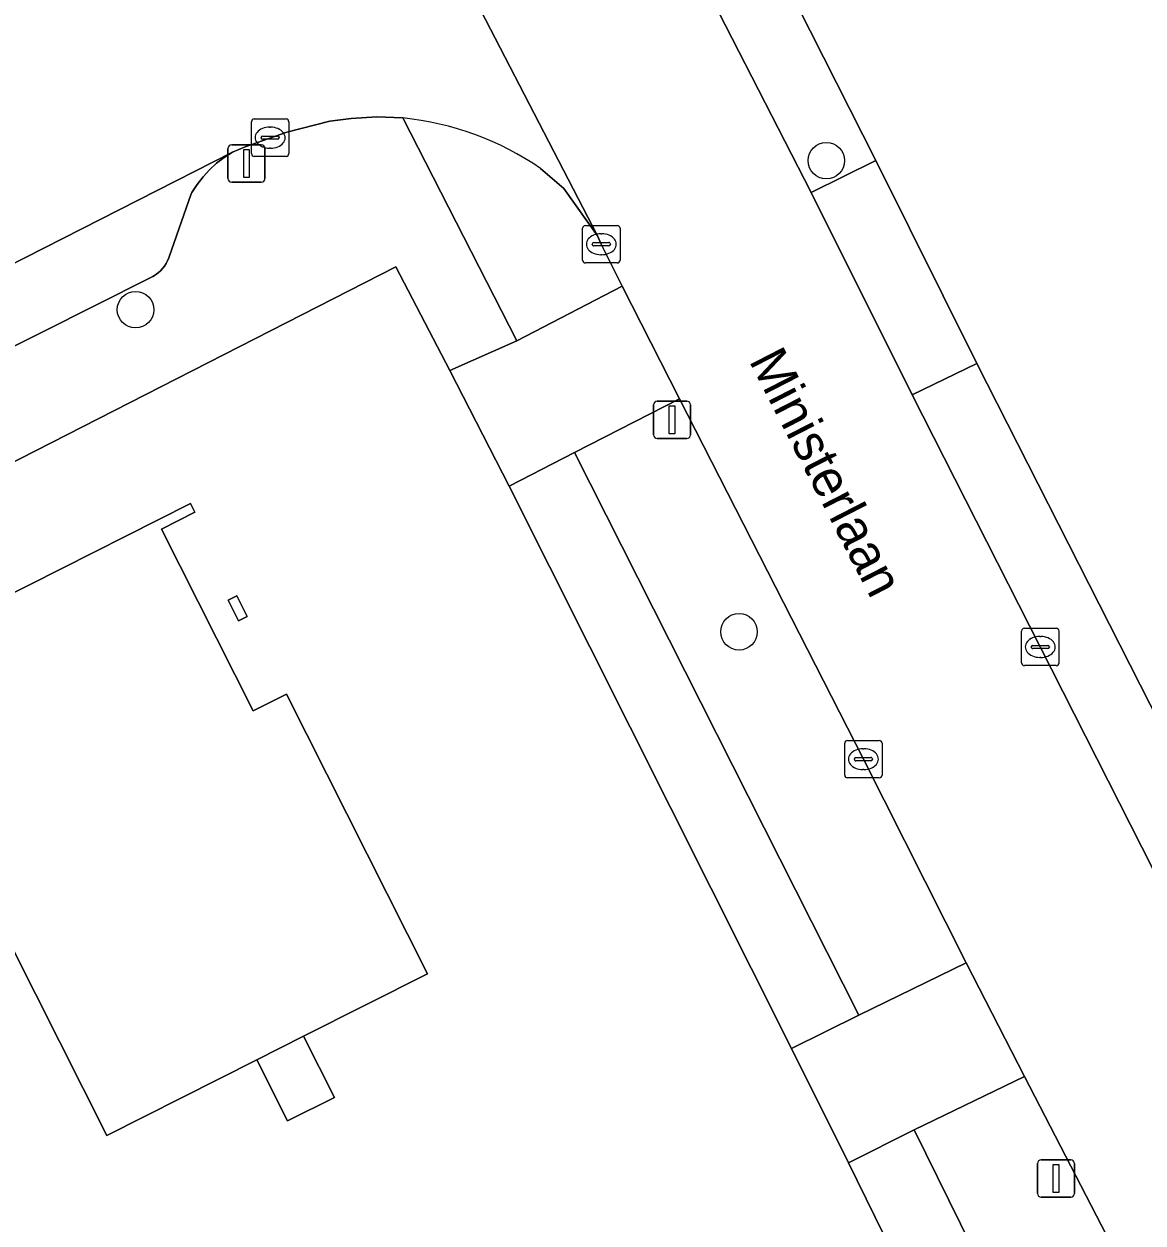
# Model space of a CAD drawing. Extents: x 162722 to 165104, y 384719 to 386284.
# Drawn here: x 163672.34 to 163702.28, y 384951.29 to 384983.38 of the extents above; entities that cross this region are included whole.
import ezdxf

# ---------------------------------------------------------------- set-up
doc = ezdxf.new("R2010")
doc.units = 0
for name, color, linetype in [('IMGEO_Boom', 7, 'Continuous'), ('IMGEO_Erf', 7, 'Continuous'), ('IMGEO_Groenvoorziening', 7, 'Continuous'), ('IMGEO_Kolk', 7, 'Continuous'), ('IMGEO_Lichtmast', 7, 'Continuous'), ('IMGEO_Openbare_ruimte_label', 7, 'Continuous'), ('IMGEO_Pand', 7, 'Continuous'), ('IMGEO_Parkeervlak_open', 7, 'Continuous'), ('IMGEO_Rijbaan_lokaal_open', 7, 'Continuous'), ('IMGEO_Verkeerseiland_groen', 7, 'Continuous'), ('IMGEO_Voetpad_open', 7, 'Continuous')]:
    doc.layers.add(name, color=color, linetype=linetype)

msp = doc.modelspace()

# ---------------------------------------------------------------- linework, layer by layer
at = {"layer": 'IMGEO_Boom'}
for centre in [(163693.809, 384979.719), (163675.327, 384975.73), (163691.473, 384967.11)]:
    msp.add_circle(centre, 0.489, dxfattribs=at)
at = {"layer": 'IMGEO_Erf'}
for points in [[(163757.669, 384995.182), (163755.228, 385000), (163754.144, 385002.139), (163753.91, 385002.58), (163753.157, 385003.995), (163752.338, 385003.569), (163740.176, 385027.426), (163738.567, 385026.557), (163738.822, 385026.058), (163738.155, 385025.71), (163714.087, 385013.147), (163707.49, 385026.219), (163704.586, 385031.975), (163675.935, 385017.371), (163676.458, 385016.283), (163679.164, 385010.981), (163682.06, 385005.355), (163684.816, 385000), (163686.673, 384996.393), (163688.473, 384992.888), (163695.133, 384979.723), (163697.839, 384974.289), (163705.48, 384959.251), (163707.512, 384955.385)], [(163689.085, 384888.134), (163687.084, 384890.632), (163676.468, 384903.753), (163673.969, 384906.848), (163673.753, 384907.134), (163665.55, 384917.268), (163665.421, 384917.261), (163660.75, 384923.114), (163663.751, 384924.681), (163669.399, 384920.052), (163676.37, 384925.254), (163699.363, 384942.796), (163694.404, 384952.9), (163692.876, 384955.959), (163685.319, 384971.004), (163683.732, 384974.099), (163682.29, 384976.876), (163639.563, 384955.061), (163635.539, 384952.364), (163633.451, 384950.624), (163627.464, 384944.399)]]:
    msp.add_lwpolyline(points, dxfattribs=at)
for points in [[(163679.396, 384954.019), (163678.57, 384955.657), (163674.556, 384953.632), (163671.374, 384959.94), (163662.971, 384955.701), (163662.466, 384956.703), (163660.215, 384961.167), (163666.964, 384964.571), (163667.958, 384962.602), (163669.574, 384963.417), (163668.587, 384965.373), (163668.173, 384966.193), (163676.793, 384970.541), (163676.91, 384970.309), (163676.019, 384969.859), (163678.473, 384964.994), (163679.364, 384965.444), (163683.138, 384957.961), (163679.824, 384956.289), (163680.65, 384954.651)], [(163677.805, 384967.96), (163678.036, 384968.077), (163678.315, 384967.523), (163678.084, 384967.407)]]:
    msp.add_lwpolyline(points, close=True, dxfattribs=at)
at = {"layer": 'IMGEO_Groenvoorziening'}
msp.add_lwpolyline([(163697.55, 384958.253), (163694.801, 384963.702), (163689.884, 384973.343), (163687.069, 384971.907), (163694.677, 384956.848)], close=True, dxfattribs=at)
msp.add_lwpolyline([(163703.08, 384947.428), (163701.856, 384949.895), (163699.111, 384955.206), (163696.161, 384953.784), (163702.06, 384941.801)], dxfattribs=at)
at = {"layer": 'IMGEO_Kolk'}
for p, q in [((163678.427, 384979.908), (163678.427, 384980.76)), ((163678.502, 384980.834), (163679.354, 384980.834)), ((163679.428, 384980.76), (163679.428, 384979.908)), ((163678.686, 384980.328), (163678.686, 384980.34)), ((163678.729, 384980.377), (163679.127, 384980.377)), ((163678.915, 384980.614), (163678.94, 384980.614)), ((163679.17, 384980.34), (163679.17, 384980.328)), ((163679.124, 384980.291), (163678.726, 384980.291)), ((163678.938, 384980.054), (163678.913, 384980.054)), ((163679.354, 384979.834), (163678.502, 384979.834)), ((163687.288, 384977.056), (163687.288, 384977.908)), ((163687.363, 384977.982), (163688.215, 384977.982)), ((163687.776, 384977.762), (163687.801, 384977.762)), ((163688.289, 384977.908), (163688.289, 384977.056)), ((163687.547, 384977.476), (163687.547, 384977.488)), ((163687.985, 384977.439), (163687.587, 384977.439)), ((163687.59, 384977.525), (163687.988, 384977.525)), ((163688.031, 384977.488), (163688.031, 384977.476)), ((163687.799, 384977.202), (163687.774, 384977.202)), ((163688.215, 384976.982), (163687.363, 384976.982)), ((163699.108, 384967.204), (163699.96, 384967.204)), ((163699.033, 384966.278), (163699.033, 384967.13)), ((163699.521, 384966.984), (163699.546, 384966.984)), ((163700.034, 384967.13), (163700.034, 384966.278)), ((163699.292, 384966.698), (163699.292, 384966.71)), ((163699.73, 384966.661), (163699.332, 384966.661)), ((163699.335, 384966.747), (163699.733, 384966.747)), ((163699.776, 384966.71), (163699.776, 384966.698)), ((163699.96, 384966.204), (163699.108, 384966.204)), ((163699.544, 384966.424), (163699.519, 384966.424)), ((163694.3, 384963.276), (163694.3, 384964.128)), ((163694.375, 384964.202), (163695.227, 384964.202)), ((163694.788, 384963.982), (163694.813, 384963.982)), ((163695.301, 384964.128), (163695.301, 384963.276)), ((163694.559, 384963.696), (163694.559, 384963.708)), ((163694.997, 384963.659), (163694.599, 384963.659)), ((163694.602, 384963.745), (163695, 384963.745)), ((163695.043, 384963.708), (163695.043, 384963.696)), ((163694.811, 384963.422), (163694.786, 384963.422)), ((163695.227, 384963.202), (163694.375, 384963.202))]:
    msp.add_line(p, q, dxfattribs=at)
for points in [[(163678.427, 384979.908), (163678.427, 384980.76)], [(163678.502, 384980.834), (163679.354, 384980.834)], [(163679.428, 384980.76), (163679.428, 384979.908)], [(163679.354, 384979.834), (163678.502, 384979.834)], [(163687.288, 384977.056), (163687.288, 384977.908)], [(163687.363, 384977.982), (163688.215, 384977.982)], [(163688.289, 384977.908), (163688.289, 384977.056)], [(163688.215, 384976.982), (163687.363, 384976.982)], [(163699.108, 384967.204), (163699.96, 384967.204)], [(163699.033, 384966.278), (163699.033, 384967.13)], [(163700.034, 384967.13), (163700.034, 384966.278)], [(163699.96, 384966.204), (163699.108, 384966.204)], [(163694.3, 384963.276), (163694.3, 384964.128)], [(163694.375, 384964.202), (163695.227, 384964.202)], [(163695.301, 384964.128), (163695.301, 384963.276)], [(163695.227, 384963.202), (163694.375, 384963.202)]]:
    msp.add_lwpolyline(points, dxfattribs=at)
for centre, radius, start, end in [((163678.504, 384980.758), 0.0765, 91.552, 178.448), ((163678.504, 384980.758), 0.0765, 91.552, 178.448), ((163679.352, 384980.758), 0.0765, 1.552, 88.448), ((163679.352, 384980.758), 0.0765, 1.552, 88.448), ((163678.726, 384980.337), 0.0403, 85.8775, 175.7526), ((163678.723, 384980.327), 0.0366, 178.938, 274.7102), ((163679.127, 384980.334), 0.043, 264.8664, 352.4533), ((163679.131, 384980.339), 0.0386, 1.7309, 96.639), ((163678.504, 384979.91), 0.0765, 181.552, 268.448), ((163678.504, 384979.91), 0.0765, 181.552, 268.448), ((163679.352, 384979.91), 0.0765, 271.552, 358.448), ((163679.352, 384979.91), 0.0765, 271.552, 358.448), ((163687.365, 384977.906), 0.0765, 91.552, 178.448), ((163687.365, 384977.906), 0.0765, 91.552, 178.448), ((163688.213, 384977.906), 0.0765, 1.552, 88.448), ((163688.213, 384977.906), 0.0765, 1.552, 88.448), ((163687.587, 384977.485), 0.0403, 85.8775, 175.7526), ((163687.584, 384977.475), 0.0366, 178.938, 274.7102), ((163687.988, 384977.482), 0.043, 264.8664, 352.4533), ((163687.992, 384977.487), 0.0386, 1.7309, 96.639), ((163687.365, 384977.058), 0.0765, 181.552, 268.448), ((163687.365, 384977.058), 0.0765, 181.552, 268.448), ((163688.213, 384977.058), 0.0765, 271.552, 358.448), ((163688.213, 384977.058), 0.0765, 271.552, 358.448), ((163699.11, 384967.128), 0.0765, 91.552, 178.448), ((163699.11, 384967.128), 0.0765, 91.552, 178.448), ((163699.958, 384967.128), 0.0765, 1.552, 88.448), ((163699.958, 384967.128), 0.0765, 1.552, 88.448), ((163699.332, 384966.707), 0.0403, 85.8775, 175.7526), ((163699.329, 384966.697), 0.0366, 178.938, 274.7102), ((163699.733, 384966.704), 0.043, 264.8664, 352.4533), ((163699.737, 384966.709), 0.0386, 1.7309, 96.639), ((163699.11, 384966.28), 0.0765, 181.552, 268.448), ((163699.11, 384966.28), 0.0765, 181.552, 268.448), ((163699.958, 384966.28), 0.0765, 271.552, 358.448), ((163699.958, 384966.28), 0.0765, 271.552, 358.448), ((163694.377, 384964.126), 0.0765, 91.552, 178.448), ((163694.377, 384964.126), 0.0765, 91.552, 178.448), ((163695.225, 384964.126), 0.0765, 1.552, 88.448), ((163695.225, 384964.126), 0.0765, 1.552, 88.448), ((163694.599, 384963.705), 0.0403, 85.8775, 175.7526), ((163694.596, 384963.695), 0.0366, 178.938, 274.7102), ((163695, 384963.702), 0.043, 264.8664, 352.4533), ((163695.004, 384963.707), 0.0386, 1.7309, 96.639), ((163694.377, 384963.278), 0.0765, 181.552, 268.448), ((163694.377, 384963.278), 0.0765, 181.552, 268.448), ((163695.225, 384963.278), 0.0765, 271.552, 358.448), ((163695.225, 384963.278), 0.0765, 271.552, 358.448)]:
    msp.add_arc(centre, radius, start, end, dxfattribs=at)
for centre, major_axis, ratio, start_param, end_param in [((163678.914, 384980.334), (-0.387, 0.002), 0.722429, 4.712389, 7.853982), ((163678.939, 384980.334), (-0.39, 0.002), 0.717154, 1.570796, 4.712389), ((163687.775, 384977.482), (-0.387, 0.002), 0.722429, 4.712389, 7.853982), ((163687.8, 384977.482), (-0.39, 0.002), 0.717154, 1.570796, 4.712389), ((163699.52, 384966.704), (-0.387, 0.002), 0.722429, 4.712389, 7.853982), ((163699.545, 384966.704), (-0.39, 0.002), 0.717154, 1.570796, 4.712389), ((163694.787, 384963.702), (-0.387, 0.002), 0.722429, 4.712389, 7.853982), ((163694.812, 384963.702), (-0.39, 0.002), 0.717154, 1.570796, 4.712389)]:
    msp.add_ellipse(centre, major_axis=major_axis, ratio=ratio, start_param=start_param, end_param=end_param, dxfattribs=at)
at = {"layer": 'IMGEO_Lichtmast'}
for p, q in [((163677.8, 384979.242), (163677.8, 384980.042)), ((163677.8, 384980.042), (163677.8, 384979.242)), ((163677.9, 384980.142), (163678.69, 384980.142)), ((163678.69, 384980.142), (163677.9, 384980.142)), ((163678.79, 384980.042), (163678.79, 384979.242)), ((163678.79, 384979.242), (163678.79, 384980.042)), ((163678.69, 384979.142), (163677.9, 384979.142)), ((163677.9, 384979.142), (163678.69, 384979.142)), ((163689.287, 384973.285), (163690.077, 384973.285)), ((163690.077, 384973.285), (163689.287, 384973.285)), ((163689.187, 384972.385), (163689.187, 384973.185)), ((163689.187, 384973.185), (163689.187, 384972.385)), ((163690.177, 384973.185), (163690.177, 384972.385)), ((163690.177, 384972.385), (163690.177, 384973.185)), ((163690.077, 384972.285), (163689.287, 384972.285)), ((163689.287, 384972.285), (163690.077, 384972.285)), ((163699.457, 384952.08), (163699.457, 384952.88)), ((163699.457, 384952.88), (163699.457, 384952.08)), ((163699.557, 384952.98), (163700.347, 384952.98)), ((163700.347, 384952.98), (163699.557, 384952.98)), ((163700.447, 384952.88), (163700.447, 384952.08)), ((163700.447, 384952.08), (163700.447, 384952.88)), ((163700.347, 384951.98), (163699.557, 384951.98)), ((163699.557, 384951.98), (163700.347, 384951.98))]:
    msp.add_line(p, q, dxfattribs=at)
for points in [[(163678.22, 384980.017), (163678.37, 384980.017), (163678.37, 384979.267), (163678.22, 384979.267), (163678.22, 384980.017)], [(163689.607, 384973.16), (163689.757, 384973.16), (163689.757, 384972.41), (163689.607, 384972.41), (163689.607, 384973.16)], [(163699.877, 384952.855), (163700.027, 384952.855), (163700.027, 384952.105), (163699.877, 384952.105), (163699.877, 384952.855)]]:
    msp.add_lwpolyline(points, dxfattribs=at)
for centre, start, end in [((163677.9, 384980.042), 90, 180), ((163677.9, 384980.042), 90, 180), ((163678.69, 384980.042), 0, 90), ((163678.69, 384980.042), 360, 90), ((163677.9, 384979.242), 180, 270), ((163677.9, 384979.242), 180, 270), ((163678.69, 384979.242), 270, 0), ((163678.69, 384979.242), 270, 0), ((163689.287, 384973.185), 90, 180), ((163689.287, 384973.185), 90, 180), ((163690.077, 384973.185), 0, 90), ((163690.077, 384973.185), 360, 90), ((163689.287, 384972.385), 180, 270), ((163689.287, 384972.385), 180, 270), ((163690.077, 384972.385), 270, 0), ((163690.077, 384972.385), 270, 0), ((163699.557, 384952.88), 90, 180), ((163699.557, 384952.88), 90, 180), ((163700.347, 384952.88), 0, 90), ((163700.347, 384952.88), 360, 90), ((163699.557, 384952.08), 180, 270), ((163699.557, 384952.08), 180, 270), ((163700.347, 384952.08), 270, 0), ((163700.347, 384952.08), 270, 0)]:
    msp.add_arc(centre, 0.1, start, end, dxfattribs=at)
at = {"layer": 'IMGEO_Pand'}
for points in [[(163679.364, 384965.444), (163678.473, 384964.994), (163676.019, 384969.859), (163676.91, 384970.309), (163676.793, 384970.541), (163668.173, 384966.193), (163668.587, 384965.373), (163669.574, 384963.417), (163667.958, 384962.602), (163666.964, 384964.571), (163660.215, 384961.167), (163662.466, 384956.703), (163662.971, 384955.701), (163671.374, 384959.94), (163674.556, 384953.632), (163678.57, 384955.657), (163679.824, 384956.289), (163683.138, 384957.961)], [(163678.036, 384968.077), (163677.805, 384967.96), (163678.084, 384967.407), (163678.315, 384967.523)], [(163679.824, 384956.289), (163678.57, 384955.657), (163679.396, 384954.019), (163680.65, 384954.651)]]:
    msp.add_lwpolyline(points, close=True, dxfattribs=at)
at = {"layer": 'IMGEO_Parkeervlak_open'}
for points in [[(163695.133, 384979.723), (163688.473, 384992.888), (163686.744, 384992.011), (163689.884, 384985.748), (163693.405, 384978.87)], [(163705.48, 384959.251), (163697.839, 384974.289), (163696.103, 384973.454), (163699.534, 384966.704), (163703.768, 384958.355)]]:
    msp.add_lwpolyline(points, close=True, dxfattribs=at)
msp.add_lwpolyline([(163652.428, 384964.866), (163675.718, 384976.583), (163675.792, 384976.621), (163675.863, 384976.665), (163675.93, 384976.715), (163675.991, 384976.771), (163676.048, 384976.832), (163676.099, 384976.898), (163676.144, 384976.968), (163676.182, 384977.042), (163676.214, 384977.119), (163676.223, 384977.147), (163676.819, 384978.83), (163676.837, 384978.862), (163676.975, 384979.08), (163677.132, 384979.285), (163677.306, 384979.475), (163677.497, 384979.649), (163677.702, 384979.805), (163677.921, 384979.942), (163666.306, 384974.039)], dxfattribs=at)
at = {"layer": 'IMGEO_Rijbaan_lokaal_open'}
for points in [[(163686.166, 384979.51), (163686.783, 384978.976), (163687.684, 384977.706), (163679.873, 384992.805), (163679.812, 384992.892)], [(163679.873, 384992.805), (163687.684, 384977.706), (163687.789, 384977.482), (163688.346, 384976.358), (163689.884, 384973.343), (163694.801, 384963.702), (163697.55, 384958.253), (163699.111, 384955.206), (163701.856, 384949.895), (163703.08, 384947.428), (163709.401, 384938.391), (163712.452, 384935.454), (163725.854, 384922.399)], [(163707.281, 384951.821), (163705.797, 384954.524), (163703.768, 384958.355), (163699.534, 384966.704), (163696.103, 384973.454), (163693.405, 384978.87), (163689.884, 384985.748)], [(163666.306, 384974.039), (163677.921, 384979.942), (163678.259, 384980.084), (163679.377, 384980.48), (163680.527, 384980.775), (163681.095, 384980.851), (163681.787, 384980.887), (163682.479, 384980.861)]]:
    msp.add_lwpolyline(points, dxfattribs=at)
msp.add_arc((163681.688, 384972.996), 7.904, 55.4937, 84.2583, dxfattribs=at)
at = {"layer": 'IMGEO_Verkeerseiland_groen'}
for points in [[(163682.479, 384980.861), (163685.526, 384974.9), (163688.346, 384976.358), (163687.789, 384977.482), (163687.684, 384977.706), (163686.783, 384978.976)], [(163686.783, 384978.976), (163686.166, 384979.51)]]:
    msp.add_lwpolyline(points, dxfattribs=at)
msp.add_arc((163681.688, 384972.996), 7.904, 55.4937, 84.2583, dxfattribs=at)
at = {"layer": 'IMGEO_Voetpad_open'}
msp.add_lwpolyline([(163639.563, 384955.061), (163682.29, 384976.876), (163683.732, 384974.099), (163685.526, 384974.9), (163682.479, 384980.861), (163681.787, 384980.887), (163681.095, 384980.851), (163680.527, 384980.775), (163679.377, 384980.48), (163678.259, 384980.084), (163677.921, 384979.942), (163677.702, 384979.805), (163677.497, 384979.649), (163677.306, 384979.475), (163677.132, 384979.285), (163676.975, 384979.08), (163676.837, 384978.862), (163676.819, 384978.83), (163676.223, 384977.147), (163676.214, 384977.119), (163676.182, 384977.042), (163676.144, 384976.968), (163676.099, 384976.898), (163676.048, 384976.832), (163675.991, 384976.771), (163675.93, 384976.715), (163675.863, 384976.665), (163675.792, 384976.621), (163675.718, 384976.583), (163652.428, 384964.866)], dxfattribs=at)
for points in [[(163697.839, 384974.289), (163695.133, 384979.723), (163693.405, 384978.87), (163696.103, 384973.454)], [(163683.732, 384974.099), (163685.319, 384971.004), (163687.069, 384971.907), (163689.884, 384973.343), (163688.346, 384976.358), (163685.526, 384974.9)], [(163687.069, 384971.907), (163685.319, 384971.004), (163692.876, 384955.959), (163694.677, 384956.848)], [(163699.111, 384955.206), (163697.55, 384958.253), (163694.677, 384956.848), (163692.876, 384955.959), (163694.404, 384952.9), (163696.161, 384953.784)], [(163696.161, 384953.784), (163694.404, 384952.9), (163699.363, 384942.796), (163700.468, 384940.621), (163702.06, 384941.801)]]:
    msp.add_lwpolyline(points, close=True, dxfattribs=at)

# ---------------------------------------------------------------- texts
at = {"layer": 'IMGEO_Openbare_ruimte_label'}
msp.add_text('Ministerlaan', height=1, rotation=297.1797, dxfattribs=at).set_placement((163691.726, 384974.368))

doc.saveas('drawing.dxf')
